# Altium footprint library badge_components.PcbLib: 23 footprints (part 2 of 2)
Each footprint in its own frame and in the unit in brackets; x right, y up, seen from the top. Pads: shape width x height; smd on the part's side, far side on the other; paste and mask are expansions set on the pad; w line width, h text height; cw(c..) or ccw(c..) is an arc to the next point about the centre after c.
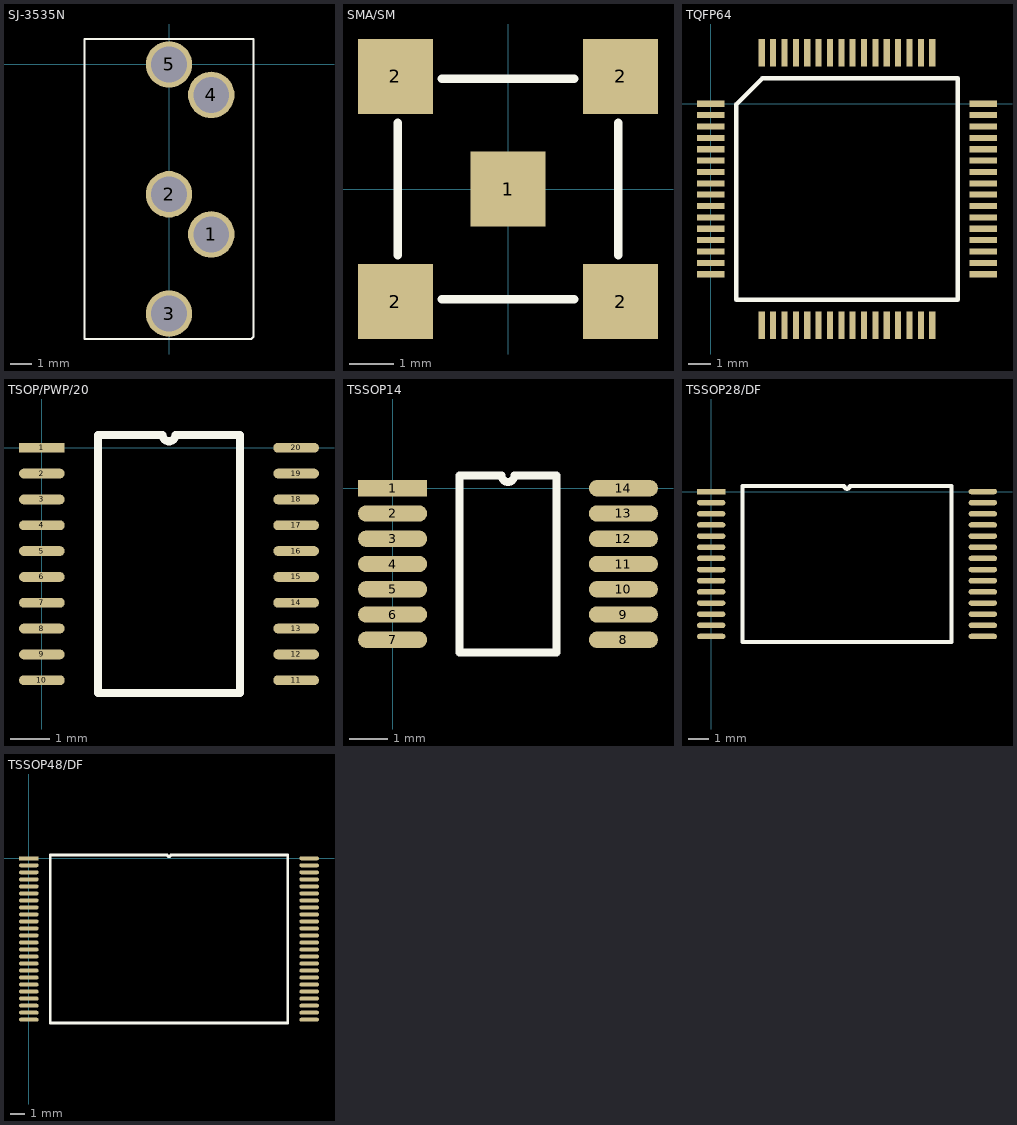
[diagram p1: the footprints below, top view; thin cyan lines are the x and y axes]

## SJ-3535N [mm]
height 12.3
pads (5):
  round 2.2 hole 1.7: 1(2,-8.05) 2(0,-6.15) 3(0,-11.8) 4(2,-1.45) 5(0,0)
Top Overlay:
  lines w0.1: -4,-13 -4,1.2 4,1.2 4,-12.9 3.9,-13 -4,-13

## SMA/SM [mm]
height 13.8
pads (5):
  rect 1.7x1.7 smd: 1(0,0) 2(-2.55,-2.55) 2(-2.55,2.55) 2(2.55,-2.55) 2(2.55,2.55)
Top Overlay:
  lines w0.2: -2.5,-1.5 -2.5,1.5 ; -1.5,-2.5 1.5,-2.5 ; -1.5,2.5 1.5,2.5 ; 2.5,-1.5 2.5,1.5

## TQFP64 [mm]
pads (64):
  rect 1.2x0.27 smd: 1(0,0) 2(0,-0.5) 3(0,-1) 4(0,-1.5) 5(0,-2) 6(0,-2.5) 7(0,-3) 8(0,-3.5) 9(0,-4) 10(0,-4.5) 11(0,-5) 12(0,-5.5) 13(0,-6) 14(0,-6.5) 15(0,-7) 16(0,-7.5) 33(12,-7.5) 34(12,-7) 35(12,-6.5) 36(12,-6) 37(12,-5.5) 38(12,-5) 39(12,-4.5) 40(12,-4) 41(12,-3.5) 42(12,-3) 43(12,-2.5) 44(12,-2) 45(12,-1.5) 46(12,-1) 47(12,-0.5) 48(12,0)
  rect 0.27x1.2 smd: 17(2.25,-9.75) 18(2.75,-9.75) 19(3.25,-9.75) 20(3.75,-9.75) 21(4.25,-9.75) 22(4.75,-9.75) 23(5.25,-9.75) 24(5.75,-9.75) 25(6.25,-9.75) 26(6.75,-9.75) 27(7.25,-9.75) 28(7.75,-9.75) 29(8.25,-9.75) 30(8.75,-9.75) 31(9.25,-9.75) 32(9.75,-9.75) 49(9.75,2.25) 50(9.25,2.25) 51(8.75,2.25) 52(8.25,2.25) 53(7.75,2.25) 54(7.25,2.25) 55(6.75,2.25) 56(6.25,2.25) 57(5.75,2.25) 58(5.25,2.25) 59(4.75,2.25) 60(4.25,2.25) 61(3.75,2.25) 62(3.25,2.25) 63(2.75,2.25) 64(2.25,2.25)
Top Overlay:
  lines w0.2: 1.135,-8.615 10.865,-8.615 10.865,1.115 2.27,1.115 1.135,-0.02 1.135,-8.615

## TSOP/PWP/20 [mm]
height 1.2
pads (20):
  rect 1.15x0.25 smd: 1(0,0)
  oval 1.15x0.25 smd: 2(0,-0.65) 3(0,-1.3) 4(0,-1.95) 5(0,-2.6) 6(0,-3.25) 7(0,-3.9) 8(0,-4.55) 9(0,-5.2) 10(0,-5.85) 11(6.4,-5.85) 12(6.4,-5.2) 13(6.4,-4.55) 14(6.4,-3.9) 15(6.4,-3.25) 16(6.4,-2.6) 17(6.4,-1.95) 18(6.4,-1.3) 19(6.4,-0.65) 20(6.4,0)
Top Overlay:
  lines w0.2: 1.41,-6.175 4.99,-6.175 4.99,0.325 3.362,0.325 cw(c3.2,0.325) 3.037,0.325 1.41,0.325 1.41,-6.175

## TSSOP14 [mm]
pads (14):
  rect 1.78x0.42 smd: 1(0,0)
  oval 1.78x0.42 smd: 2(0,-0.65) 3(0,-1.3) 4(0,-1.95) 5(0,-2.6) 6(0,-3.25) 7(0,-3.9) 8(5.94,-3.9) 9(5.94,-3.25) 10(5.94,-2.6) 11(5.94,-1.95) 12(5.94,-1.3) 13(5.94,-0.65) 14(5.94,0)
Top Overlay:
  lines w0.2: 1.725,-4.225 4.215,-4.225 4.215,0.325 3.132,0.325 cw(c2.97,0.325) 2.808,0.325 1.725,0.325 1.725,-4.225

## TSSOP28/DF [mm]
pads (28):
  rect 1.4x0.27 smd: 1(0,0)
  oval 1.4x0.27 smd: 2(0,-0.55) 3(0,-1.1) 4(0,-1.65) 5(0,-2.2) 6(0,-2.75) 7(0,-3.3) 8(0,-3.85) 9(0,-4.4) 10(0,-4.95) 11(0,-5.5) 12(0,-6.05) 13(0,-6.6) 14(0,-7.15) 15(13.4,-7.15) 16(13.4,-6.6) 17(13.4,-6.05) 18(13.4,-5.5) 19(13.4,-4.95) 20(13.4,-4.4) 21(13.4,-3.85) 22(13.4,-3.3) 23(13.4,-2.75) 24(13.4,-2.2) 25(13.4,-1.65) 26(13.4,-1.1) 27(13.4,-0.55) 28(13.4,0)
Top Overlay:
  lines w0.2: 1.535,-7.425 1.535,0.275 6.563,0.275 ccw(c6.7,0.275) 6.837,0.275 11.865,0.275 11.865,-7.425 1.535,-7.425

## TSSOP48/DF [mm]
pads (48):
  rect 1.4x0.27 smd: 1(0,0)
  oval 1.4x0.27 smd: 2(0,-0.5) 3(0,-1) 4(0,-1.5) 5(0,-2) 6(0,-2.5) 7(0,-3) 8(0,-3.5) 9(0,-4) 10(0,-4.5) 11(0,-5) 12(0,-5.5) 13(0,-6) 14(0,-6.5) 15(0,-7) 16(0,-7.5) 17(0,-8) 18(0,-8.5) 19(0,-9) 20(0,-9.5) 21(0,-10) 22(0,-10.5) 23(0,-11) 24(0,-11.5) 25(20,-11.5) 26(20,-11) 27(20,-10.5) 28(20,-10) 29(20,-9.5) 30(20,-9) 31(20,-8.5) 32(20,-8) 33(20,-7.5) 34(20,-7) 35(20,-6.5) 36(20,-6) 37(20,-5.5) 38(20,-5) 39(20,-4.5) 40(20,-4) 41(20,-3.5) 42(20,-3) 43(20,-2.5) 44(20,-2) 45(20,-1.5) 46(20,-1) 47(20,-0.5) 48(20,0)
Top Overlay:
  lines w0.2: 1.535,-11.75 1.535,0.25 9.875,0.25 ccw(c10,0.25) 10.125,0.25 18.465,0.25 18.465,-11.75 1.535,-11.75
